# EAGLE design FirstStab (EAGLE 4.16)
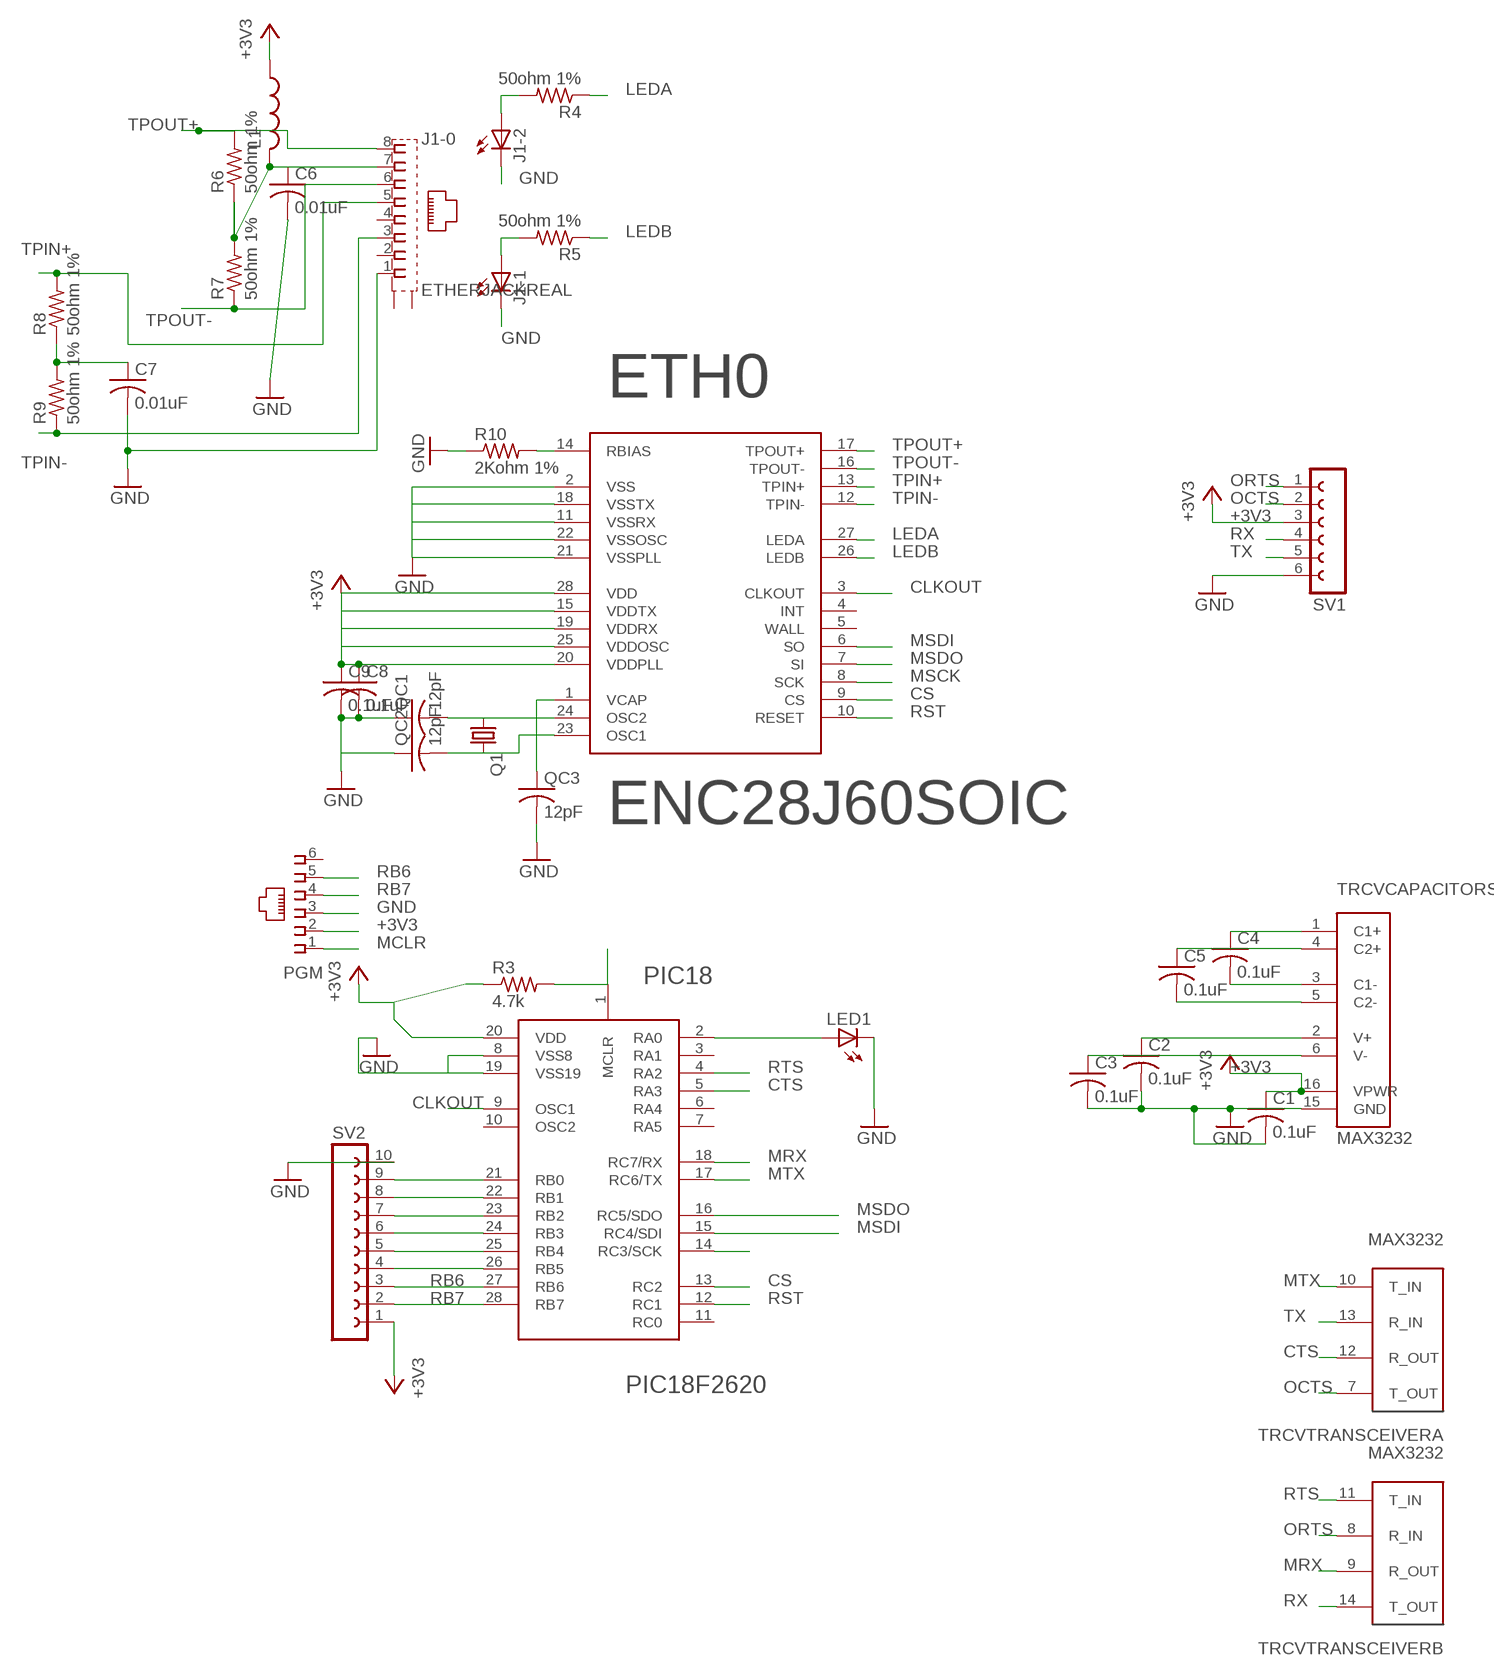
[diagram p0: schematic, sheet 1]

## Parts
C1  0.1uF  C-US025-024X044  [C025-024X044]
C2  0.1uF  C-US025-024X044  [C025-024X044]
C3  0.1uF  C-US025-024X044  [C025-024X044]
C4  0.1uF  C-US025-024X044  [C025-024X044]
C5  0.1uF  C-US025-024X044  [C025-024X044]
C6  0.01uF  C-US050-035X075  [C050-035X075]
C7  0.01uF  C-US050-035X075  [C050-035X075]
C8  0.1uF  C-US025-024X044  [C025-024X044]
C9  0.1uF  C-US025-024X044  [C025-024X044]
ETH0  ENC28J60SOIC  [SO-28W]
J1  ETHERJACKREAL  [0569564]
L1  L-US0204/5  [0204/5]
LED1  LED3MM  [LED3MM]
PGM  520470-3  [520470-3]
PIC18  PIC18F2620  [SO-28W]
Q1  CRYTALHC49U-H  [HC49U-H]
QC1  12pF  C-US050-024X044  [C050-024X044]
QC2  12pF  C-US050-024X044  [C050-024X044]
QC3  12pF  C-US025-024X044  [C025-024X044]
R3  4.7k  R-US_0207/7  [0207/7]
R4  50ohm 1%  R-US_0204/5  [0204/5]
R5  50ohm 1%  R-US_0204/5  [0204/5]
R6  50ohm 1%  R-US_0204/5  [0204/5]
R7  50ohm 1%  R-US_0204/5  [0204/5]
R8  50ohm 1%  R-US_0204/5  [0204/5]
R9  50ohm 1%  R-US_0204/5  [0204/5]
R10  2Kohm 1%  R-US_0204/5  [0204/5]
SV1  FE06-1  [FE06]
SV2  FE10-1  [FE10]
TRCV  MAX3232  MAX3232FOO  [SO16]

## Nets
+3V3: C1.1 C8.1 C9.1 ETH0.15(VDDTX) ETH0.19(VDDRX) ETH0.20(VDDPLL) ETH0.25(VDDOSC) ETH0.28(VDD) L1.1 PGM.2 PIC18.20(VDD) R3.1 SV1.3 SV2.1 TRCV.16(CAPACITORS:VPWR)
CLKOUT: ETH0.3(CLKOUT) PIC18.9(OSC1)
CS: ETH0.9(CS) PIC18.13(RC2)
CTS: PIC18.5(RA3) TRCV.12(TRANSCEIVERA:R_OUT)
GND: C1.2 C2.2 C3.2 C6.2 C7.2 C8.2 C9.2 ETH0.2(VSS) ETH0.11(VSSRX) ETH0.18(VSSTX) ETH0.21(VSSPLL) ETH0.22(VSSOSC) J1.1 J1.A2(-2:C) J1.C1(-1:C) LED1.K(C) PGM.3 PIC18.8(VSS8) PIC18.19(VSS19) QC1.1 QC2.1 QC3.2 R10.1 SV1.6 SV2.10 TRCV.15(CAPACITORS:GND)
LEDA: ETH0.27(LEDA) R4.1
LEDB: ETH0.26(LEDB) R5.1
MCLR: PGM.1 PIC18.1(MCLR) R3.2
MRX: PIC18.18(RC7/RX) TRCV.9(TRANSCEIVERB:R_OUT)
MSCK: ETH0.8(SCK) PIC18.14(RC3/SCK)
MSDI: ETH0.6(SO) PIC18.15(RC4/SDI)
MSDO: ETH0.7(SI) PIC18.16(RC5/SDO)
MTX: PIC18.17(RC6/TX) TRCV.10(TRANSCEIVERA:T_IN)
N$1: ETH0.24(OSC2) Q1.1 QC1.2
N$2: ETH0.23(OSC1) Q1.2 QC2.2
N$5: ETH0.1(VCAP) QC3.1
N$6: C4.1 TRCV.1(CAPACITORS:C1+)
N$7: C5.1 TRCV.4(CAPACITORS:C2+)
N$8: C4.2 TRCV.3(CAPACITORS:C1-)
N$9: C5.2 TRCV.5(CAPACITORS:C2-)
N$10: C2.1 TRCV.2(CAPACITORS:V+)
N$11: C3.1 TRCV.6(CAPACITORS:V-)
N$14: C6.1 J1.7 L1.2 R6.1 R7.2
N$15: C7.1 R8.1 R9.2
N$16: J1.C2(-2:A) R4.2
N$17: J1.A1(-1:A) R5.2
N$19: ETH0.14(RBIAS) R10.2
N$25: LED1.A PIC18.2(RA0)
N$26: PIC18.21(RB0) SV2.9
N$30: PIC18.22(RB1) SV2.8
N$31: PIC18.23(RB2) SV2.7
N$32: PIC18.24(RB3) SV2.6
N$33: PIC18.25(RB4) SV2.5
N$34: PIC18.26(RB5) SV2.4
OCTS: SV1.2 TRCV.7(TRANSCEIVERA:T_OUT)
ORTS: SV1.1 TRCV.8(TRANSCEIVERB:R_IN)
RB6: PGM.5 PIC18.27(RB6) SV2.3
RB7: PGM.4 PIC18.28(RB7) SV2.2
RST: ETH0.10(RESET) PIC18.12(RC1)
RTS: PIC18.4(RA2) TRCV.11(TRANSCEIVERB:T_IN)
RX: SV1.4 TRCV.14(TRANSCEIVERB:T_OUT)
TPIN+: ETH0.13(TPIN+) J1.5 R8.2
TPIN-: ETH0.12(TPIN-) J1.3 R9.1
TPOUT+: ETH0.17(TPOUT+) J1.8 R6.2
TPOUT-: ETH0.16(TPOUT-) J1.6 R7.1
TX: SV1.5 TRCV.13(TRANSCEIVERA:R_IN)
Unconnected: ETH0.4(INT) ETH0.5(WALL) J1.2 J1.4 J1.S1(-0:S1) J1.S2(-0:S2) PGM.6 PIC18.3(RA1) PIC18.6(RA4) PIC18.7(RA5) PIC18.10(OSC2) PIC18.11(RC0)

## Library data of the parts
C1-C9 QC1-QC3 = rcl:C-US: CAPACITOR, American symbol
ETH0 = serial_ethernet_parts:ENC28J60
J1 = etherjack:ETHERJACK: MODULAR JACK 8 POS., RIGHT ANGLE, LOW PROFILE WITH LEDS Source: http://ecommas.tycoelectronics.com/.. 569564_K.pdf
L1 = rcl:L-US: INDUCTOR, American symbol
LED1 = led:LED: LED
PGM = con-amp:520470-3: AMP connector
PIC18 = serial_ethernet_parts:PIC18F2620
Q1 = crystal:CRYTAL: CRYSTAL
R3-R10 = rcl:R-US_: RESISTOR, American symbol
SV1 = con-lsta:FE06-1: FEMALE HEADER
SV2 = con-lsta:FE10-1: FEMALE HEADER
TRCV = serial_ethernet_parts:MAX3232

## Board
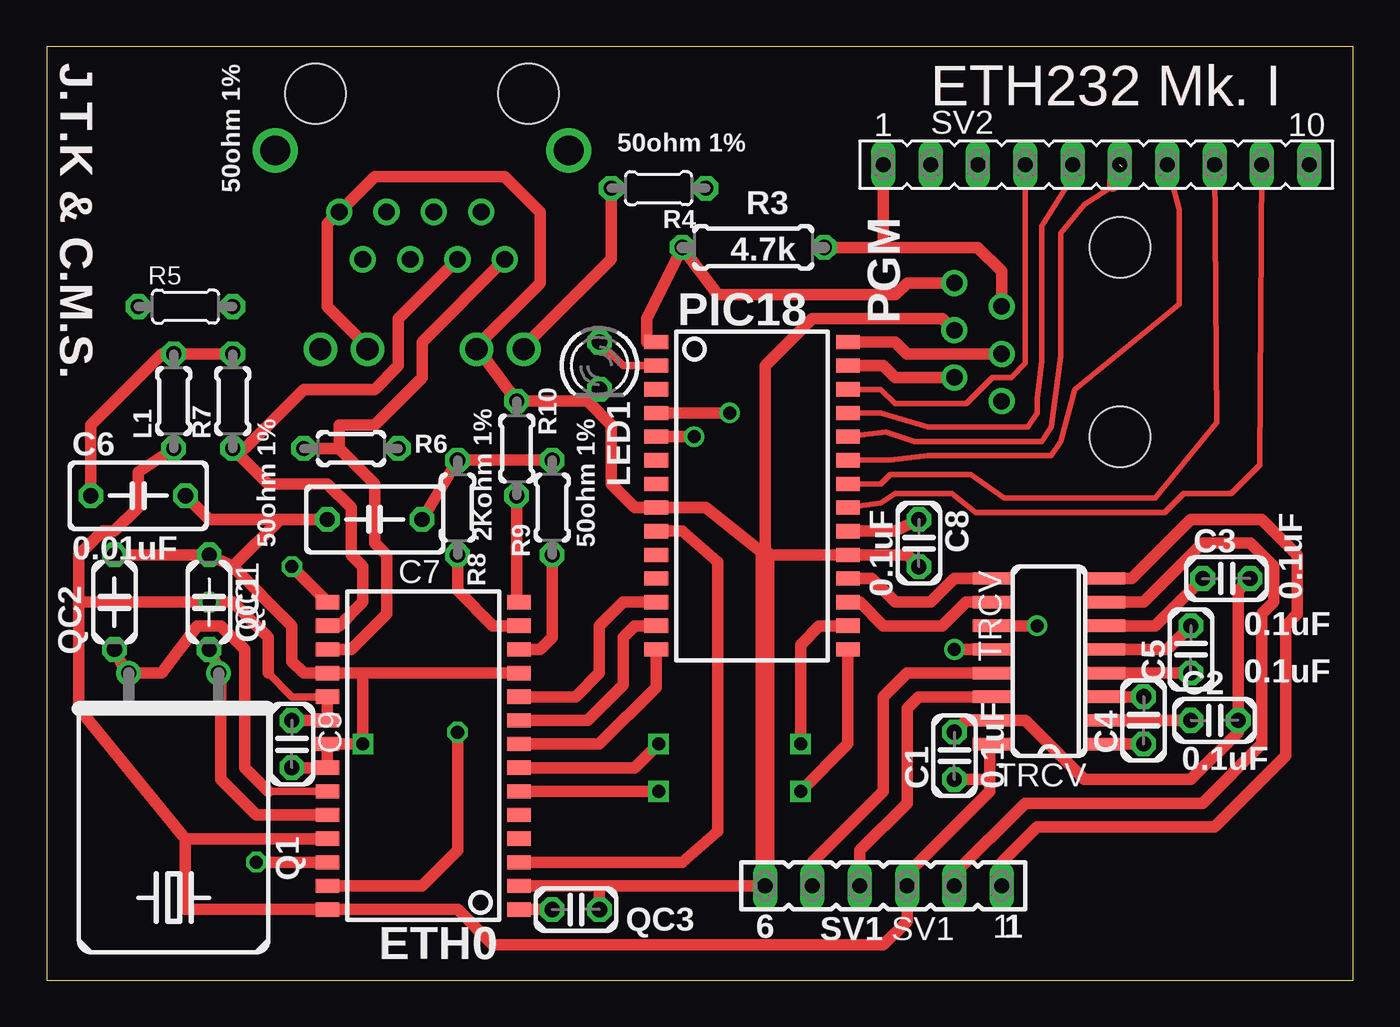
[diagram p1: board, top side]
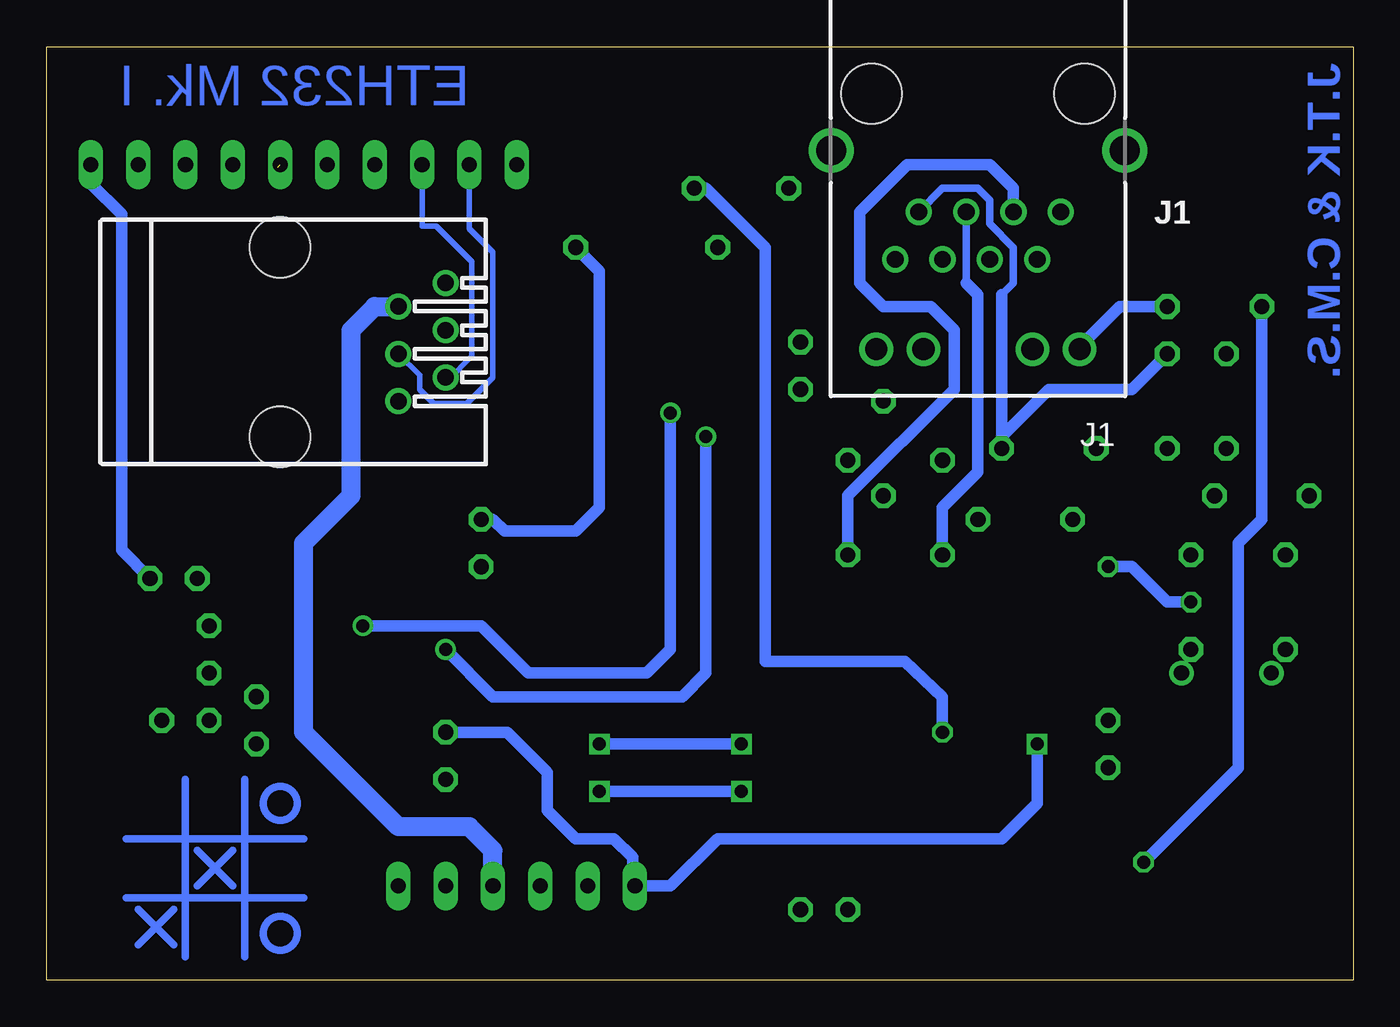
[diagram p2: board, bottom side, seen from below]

Size 70.16 x 50.16 mm. Coordinates in mm from the lower left corner, seen from the top.
Outline: 0,0 70.16,0 70.16,50.16 0,50.16 0,0
Copper layers (1*16): Top 0.035mm / dielectric 1.5mm / Bottom 0.035mm
Design rules "10mils": minimum track width 10mil, minimum drill 24mil, track to track 10mil, track to pad 10mil, pad to pad 10mil, via to via 10mil, smd to smd 10mil, copper to edge 40mil, drill to drill 10mil, minimum pad ring 10mil, minimum via ring 8mil, stop-mask expansion 0mil, vias tented up to drill 0mil, thermal gap 10mil

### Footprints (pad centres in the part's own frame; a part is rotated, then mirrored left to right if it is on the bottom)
C025-024X044 = drill 0.813 octagon: 1 -1.27,0; 2 1.27,0
C050-035X075 = drill 0.813 octagon: 1 -2.54,0; 2 2.54,0
SO-28W = smd 0.762 x 1.27: 1 -7.62,-5.207; 2 -6.35,-5.207; 3 -5.08,-5.207; 4 -3.81,-5.207; 5 -2.54,-5.207; 6 -1.27,-5.207; 7 0,-5.207; 8 1.27,-5.207; 9 2.54,-5.207; 10 3.81,-5.207; 11 5.08,-5.207; 12 6.35,-5.207; 13 7.62,-5.207; 14 8.89,-5.207; 15 8.89,5.08; 16 7.62,5.08; 17 6.35,5.08; 18 5.08,5.08; 19 3.81,5.08; 20 2.54,5.08; 21 1.27,5.08; 22 0,5.08; 23 -1.27,5.08; 24 -2.54,5.08; 25 -3.81,5.08; 26 -5.08,5.08; 27 -6.35,5.08; 28 -7.62,5.08
0569564 = drill 0.9 round: 1 -4.445,6.35; 2 -3.175,8.89; 3 -1.905,6.35; 4 -0.635,8.89; 5 0.635,6.35; 6 1.905,8.89; 7 3.175,6.35; 8 4.445,8.89 | drill 1.2 round: A1 -5.461,13.716; A2 2.921,13.716; C1 -2.921,13.716; C2 5.461,13.716 | drill 1.6 pad 1.93 round: S1 -7.874,3.048; S2 7.874,3.048 | hole 3.25: -5.715,0; 5.715,0
0204/5 = drill 0.813 octagon: 1 -2.54,0; 2 2.54,0
LED3MM = drill 0.813 octagon: A -1.27,0; K 1.27,0
520470-3 = drill 0.889 round: 1 -3.175,8.89; 2 -1.905,6.35; 3 -0.635,8.89; 4 0.635,6.35; 5 1.905,8.89; 6 3.175,6.35 | hole 3.251: -5.08,0; 5.08,0
HC49U-H = drill 0.813 round: 1 -2.413,-5.08; 2 2.413,-5.08
C050-024X044 = drill 0.813 octagon: 1 -2.54,0; 2 2.54,0
0207/7 = drill 0.813 octagon: 1 -3.81,0; 2 3.81,0
FE06 = drill 0.813 long: 1 -6.35,0; 2 -3.81,0; 3 -1.27,0; 4 1.27,0; 5 3.81,0; 6 6.35,0
FE10 = drill 0.813 long: 1 -11.43,0; 2 -8.89,0; 3 -6.35,0; 4 -3.81,0; 5 -1.27,0; 6 1.27,0; 7 3.81,0; 8 6.35,0; 9 8.89,0; 10 11.43,0
SO16 = smd 0.66 x 2.032: 1 -4.445,-3.073; 2 -3.175,-3.073; 3 -1.905,-3.073; 4 -0.635,-3.073; 5 0.635,-3.073; 6 1.905,-3.073; 7 3.175,-3.073; 8 4.445,-3.073; 9 4.445,3.073; 10 3.175,3.073; 11 1.905,3.073; 12 0.635,3.073; 13 -0.635,3.073; 14 -1.905,3.073; 15 -3.175,3.073; 16 -4.445,3.073

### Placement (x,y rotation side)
C1  48.73,12.06 90 top
C2  62.7,13.96 0 top
C3  63.33,21.59 0 top
C4  58.89,13.96 90 top
C5  61.43,17.78 90 top
C6  4.91,26.03 0 top
C7  17.62,24.76 180 top
C8  46.82,23.49 270 top
C9  13.17,12.7 270 top
ETH0  20.16,11.42 90 top
J1  20.16,47.62 180 bottom
L1  6.82,31.11 90 top
LED1  29.68,33.02 270 top
PGM  57.62,34.29 270 bottom
PIC18  37.93,26.67 270 top
Q1  6.82,11.42 180 top
QC1  8.72,20.32 270 top
QC2  3.65,20.32 270 top
QC3  28.41,3.81 0 top
R3  37.93,39.37 180 top
R4  32.85,42.54 180 top
R5  7.46,36.19 0 top
R6  16.35,28.57 180 top
R7  9.99,31.11 90 top
R8  22.06,25.4 270 top
R9  27.14,25.4 90 top
R10  25.24,28.57 270 top
SV1  44.92,5.07 180 top
SV2  56.35,43.81 0 top
TRCV  53.81,17.14 90 top

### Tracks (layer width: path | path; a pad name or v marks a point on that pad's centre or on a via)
+3V3  (via drill 0.7)
  Top 0.305: 45.05,39.37 44.92,39.49
  Top 0.406: ETH0.19 13.17,15.24 11.9,16.51
  Top 0.61: ETH0.19 ETH0.20 C9.1 | 7.46,7.62 ETH0.25 | 7.46,7.62 7.46,3.81 ETH0.28 22.06,3.81 23.96,1.9 44.92,1.9 46.19,3.17 SV1.3 46.19,5.71 50.63,10.15 50.63,10.79 | L1.1 4.91,27.3 4.91,25.4 3.65,24.12 3.01,24.12 1.74,22.86 1.74,20.32 | PGM.2 51.27,38.09 50,39.37 45.05,39.37 R3.1 | 1.74,20.32 1.74,14.6 7.46,7.62 | 11.9,16.51 11.9,18.41 9.99,20.32 v8.72,20.32 1.74,20.32 | 50.63,12.7 TRCV.16 | 50.63,12.7 50.74,12.59 | 50.63,10.79 50.63,12.7 | C8.1 45.55,24.12 PIC18.20 | 50.63,10.79 C1.1 | v13.17,22.22 ETH0.15 | 44.92,39.49 SV2.1
  Bottom 0.61: v8.72,20.32 9.99,20.32 11.9,22.22 v13.17,22.22 | C8.1 46.19,24.76 45.55,24.12 41.74,24.12 40.47,25.4 40.47,38.09 R3.1
  Bottom 1.016: PGM.2 52.54,36.19 53.81,34.92 53.81,26.03 56.35,23.49 56.35,13.33 51.27,8.25 47.46,8.25 46.19,6.98 SV1.3
CLKOUT
  Top 0.61: PIC18.9 34.12,24.12 36.03,22.47 36.03,8 34.12,6.35 ETH0.3 26.51,6.35
CS
  Top 0.61: PIC18.13 31.59,19.05 30.95,18.41 30.95,15.87 29.05,13.96 ETH0.9
CTS  (via drill 0.7)
  Top 0.61: 50.63,17.78 TRCV.12 v48.73,17.78 | v34.76,29.21 PIC18.5
  Bottom 0.61: v34.76,29.21 34.76,16.51 36.03,15.24 46.19,15.24 v48.73,17.78
GND  (via drill 0.7)
  Top 0.406: 29.05,31.11 LED1.K
  Top 0.61: QC2.1 QC1.1 9.99,22.22 | 16.98,16.51 ETH0.18 13.8,16.51 13.17,17.14 13.17,19.05 9.99,22.22 | 16.98,16.51 ETH0.11 | 16.98,16.51 v16.98,12.7 ETH0.21 ETH0.22 C9.2 | 32.22,25.4 PIC18.8 35.39,25.4 | 38.57,22.86 PIC18.19 46.19,22.86 C8.2 | 38.57,22.86 35.39,25.4 | PGM.3 48.09,35.55 41.11,35.55 38.57,33.02 38.57,22.86 | C3.2 63.97,20.95 C2.2 63.97,13.33 61.43,10.79 55.71,10.79 52.54,13.96 TRCV.15 49.36,13.96 C1.2 | 12.54,24.76 C7.2 | 12.54,24.76 8.72,24.76 C6.2 | 35.39,25.4 32.22,25.4 | 32.22,25.4 31.59,25.4 30.32,26.67 30.32,29.84 29.05,31.11 R10.1 23.08,34.03 | 9.99,22.22 12.54,24.76 | 25.24,5.07 ETH0.2 29.68,5.07 | SV1.6 29.68,5.07 | 29.68,5.07 QC3.2 | 16.98,34.29 J1.C1 17.23,34.03 16.98,34.29 | 16.98,34.29 15.08,36.19 15.08,40.63 J1.1 17.62,43.18 24.6,43.18 26.51,41.27 26.51,37.46 23.08,34.03 | 23.08,34.03 J1.A2
  Top 1.016: SV1.6 38.57,22.86
  Bottom 0.61: SV2.10 67.78,42.79 66.13,41.14 66.13,23.11 C3.2 | C1.2 45.43,13.33 43.27,11.17 43.27,9.14 41.74,7.62 39.71,7.62 38.7,6.6 38.7,5.07 38.57,4.95 | 38.57,4.95 38.44,4.82 | 38.57,4.95 SV1.6 36.66,5.07 34.12,7.62 18.89,7.62 16.98,9.52 v16.98,12.7
LEDA  (via drill 0.7)
  Top 0.61: v22.06,13.33 22.06,6.98 20.16,5.07 ETH0.27
  Bottom 0.61: v22.06,13.33 22.06,15.24 24.09,17.14 31.59,17.14 31.59,39.37 34.76,42.54 R4.1
LEDB  (via drill 0.7)
  Top 0.61: v11.26,6.35 ETH0.26
  Bottom 0.61: v11.26,6.35 6.19,11.42 6.19,23.49 4.91,24.76 R5.1
MCLR
  Top 0.61: PIC18.1 32.22,34.29 32.22,35.55 R3.2 36.03,36.83 45.55,36.83 46.19,37.46 PGM.1
MRX
  Top 0.61: PIC18.18 44.28,21.59 45.55,20.32 47.46,20.32 48.73,21.59 TRCV.9
MSCK
  Top 0.61: PIC18.14 32.73,15.74 29.68,12.7 ETH0.8 26.51,12.7
MSDI  (via drill 0.7)
  Top 0.61: PIC18.15 43.02,12.7 v40.47,10.15 | ETH0.6 v32.85,10.15
  Bottom 0.61: v32.85,10.15 v40.47,10.15
MSDO  (via drill 0.7)
  Top 0.61: PIC18.16 41.49,19.05 40.47,18.03 v40.47,12.7 | ETH0.7 31.59,11.42 v32.85,12.7
  Bottom 0.61: v32.85,12.7 v40.47,12.7
MTX
  Top 0.61: PIC18.17 43.65,20.32 44.92,19.05 48.09,19.05 49.36,20.32 TRCV.10
N$1
  Top 0.61: ETH0.24 11.26,8.88 9.36,10.79 9.36,16.51 | 9.36,16.51 QC1.2 | 9.36,16.51 Q1.1
N$2
  Top 0.406: 11.9,10.15 ETH0.23
  Top 0.61: QC2.2 4.28,16.51 Q1.2 6.19,16.51 8.09,19.05 9.36,19.05 10.63,17.78 10.63,11.42 11.9,10.15
N$5
  Top 0.61: 25.24,3.81 ETH0.1 QC3.1
N$6
  Top 0.61: TRCV.1 C4.1
N$7
  Top 0.61: TRCV.4 C5.1
N$8
  Top 0.61: TRCV.3 C4.2
N$9
  Top 0.61: TRCV.5 60.16,17.78 C5.2
N$10
  Top 0.61: TRCV.2 C2.1
N$11
  Top 0.61: TRCV.6 59.52,19.05 C3.1
N$12
  Bottom 0.406: 59.52,1.27 59.52,10.79
N$13
  Bottom 0.406: 62.7,1.27 62.7,10.79
N$14
  Top 0.61: R7.2 L1.2 6.19,33.65 2.38,29.84 C6.1
  Bottom 0.406: 18.89,36.83 18.25,37.46 18.25,39.37 19.52,40.63 19.52,41.91 20.16,42.54 22.06,42.54 J1.7
  Bottom 0.61: R7.2 11.9,31.75 16.35,31.75 18.89,29.21 R6.1 18.89,36.83
N$15
  Top 0.61: R9.2 R8.1 C7.1
N$16
  Top 0.61: J1.C2 25.62,34.03 30.32,38.73 R4.2
N$17
  Bottom 0.61: 14.82,33.9 15.08,33.65 | 14.82,33.9 J1.A1 | R5.2 12.54,36.19 14.82,33.9
N$18
  Bottom 0.406: 56.35,7.62 65.88,7.62
N$19
  Top 0.61: ETH0.14 25.24,20.32 R10.2
N$20
  Bottom 0.406: 56.35,4.44 65.88,4.44
N$21
  Bottom 0.406: 62.06,5.07 60.16,6.98
N$22
  Bottom 0.406: 60.16,5.07 62.06,6.98
N$23
  Bottom 0.406: 65.24,1.9 63.33,3.81
N$24
  Bottom 0.406: 63.33,1.9 65.24,3.81
N$25
  Top 0.406: PIC18.2 30.95,33.02 LED1.A
N$26
  Top 0.305: SV2.9 65.11,27.68 63.59,26.16 61.05,26.16 60.03,25.14 49.87,25.14 48.6,26.16 45.55,26.16 44.79,25.65 PIC18.21
N$30
  Top 0.305: 62.83,29.97 SV2.8 | 62.83,29.97 59.52,25.9 51.4,25.9 49.62,27.17 45.3,27.17 44.79,26.67 PIC18.22 | 62.83,29.97 62.83,30.22
N$31
  Top 0.305: SV2.7 60.79,41.4 60.79,36.32 55.21,31.75 54.45,28.95 53.94,28.19 47.33,28.19 45.3,27.94 PIC18.23
N$32  (1 unrouted)
  Top 0.305: 57.24,42.67 55.71,41.65 54.45,40.13 54.45,33.52 53.94,29.71 53.43,28.95 46.57,28.95 45.05,29.46 PIC18.24 | 57.49,42.92 57.75,43.68
  Top 0.61: 57.24,42.67 57.24,42.92 57.49,42.92
N$33
  Top 0.305: 55.08,43.18 53.43,40.51 53.43,33.27 53.17,31.24 53.17,30.48 52.67,29.71 47.33,29.71 44.79,30.48 PIC18.25 | 55.21,42.92 SV2.5
  Top 0.61: 55.08,43.18 55.21,42.92
N$34
  Top 0.305: SV2.4 52.54,33.14 51.78,32.38 50.76,32.38 49.36,30.98 45.55,30.98 44.79,31.75 PIC18.26
OCTS
  Top 0.61: TRCV.7 58.89,20.32 62.06,23.49 64.61,23.49 65.88,22.22 65.88,20.32 65.24,19.68 65.24,12.7 62.06,9.52 52.54,9.52 48.73,5.71 SV1.2
ORTS
  Top 0.61: TRCV.8 58.25,21.59 61.43,24.76 65.24,24.76 67.14,22.86 67.14,19.68 66.51,19.05 66.51,12.06 62.7,8.25 53.17,8.25 51.27,6.35 SV1.1
RB6
  Top 0.61: PIC18.27 44.92,33.02 45.55,32.38 PGM.5
  Bottom 0.305: SV2.3 50,40.51 49.24,40.51 47.33,38.6 47.33,33.52 48.6,32.25 PGM.5
RB7
  Top 0.61: PIC18.28 45.55,34.29 46.19,33.65 PGM.4
  Bottom 0.305: SV2.2 47.46,40.38 46.19,39.11 46.19,32.38 47.59,30.98 49.36,30.98 50.13,31.75 50.13,32.51 PGM.4
RST
  Top 0.61: 32.85,20.32 PIC18.12 30.95,20.32 29.68,19.05 29.68,16.51 28.41,15.24 ETH0.10
RTS  (via drill 0.7)
  Top 0.61: 50.63,19.05 TRCV.11 v53.17,19.05 | v36.66,30.48 PIC18.4
  Bottom 0.61: v53.17,19.05 46.82,19.05 44.28,16.51 37.93,16.51 36.66,17.78 v36.66,30.48
RX
  Top 0.61: SV1.4 43.65,6.98 46.19,9.52 46.19,14.6 46.82,15.24 TRCV.14
TPIN+
  Top 0.61: ETH0.13 23.96,19.05 22.06,20.95 R8.2
  Bottom 0.406: 20.79,37.46 J1.5
  Bottom 0.61: R8.2 22.06,25.4 20.16,27.3 20.16,36.83 20.79,37.46
TPIN-
  Top 0.61: 25.24,17.78 ETH0.12 26.51,17.78 27.14,18.41 R9.1
  Bottom 0.61: R9.1 27.14,26.03 21.43,31.75 21.43,34.92 22.7,36.19 25.24,36.19 26.51,37.46 26.51,41.27 23.96,43.81 19.52,43.81 18.25,42.54 J1.3
TPOUT+
  Top 0.61: ETH0.17 16.35,17.78 18.25,19.68 18.25,22.86 17.62,23.49 17.62,26.67 15.71,28.57 | 15.71,28.57 R6.2 | 15.71,28.57 15.71,29.84 17.62,29.84 20.16,32.38 20.16,34.29 J1.8
TPOUT-
  Top 0.61: ETH0.16 15.71,19.05 16.98,20.32 16.98,22.22 16.35,22.86 16.35,25.4 15.08,26.67 13.17,26.67 11.9,26.67 R7.1 10.63,28.57 13.8,31.75 17.62,31.75 18.89,33.02 18.89,35.55 J1.6
TX
  Top 0.61: SV1.5 41.11,6.35 44.92,10.15 44.92,15.24 46.19,16.51 TRCV.13
(copper drawn outside any net)
  shapes: Bottom circle x2

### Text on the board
Top: J.T.K & C.M.S. | ETH232 Mk. I
Bottom: J.T.K & C.M.S. | ETH232 Mk. I
tPlace: J.T.K & C.M.S. | ETH232 Mk. I
tNames: 50ohm 1% | 50ohm 1% | 4.7k | 2Kohm 1% | L1 | R7 | 0.1uF | C8 | 50ohm 1% | 50ohm 1% | 0.01uF | C3 | QC1 | 0.1uF | 0.1uF | 0.1uF | C5 | C2 | C4 | 0.1uF | C1 | 0.1uF | 6 | SV1 | 1
bNames: J1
